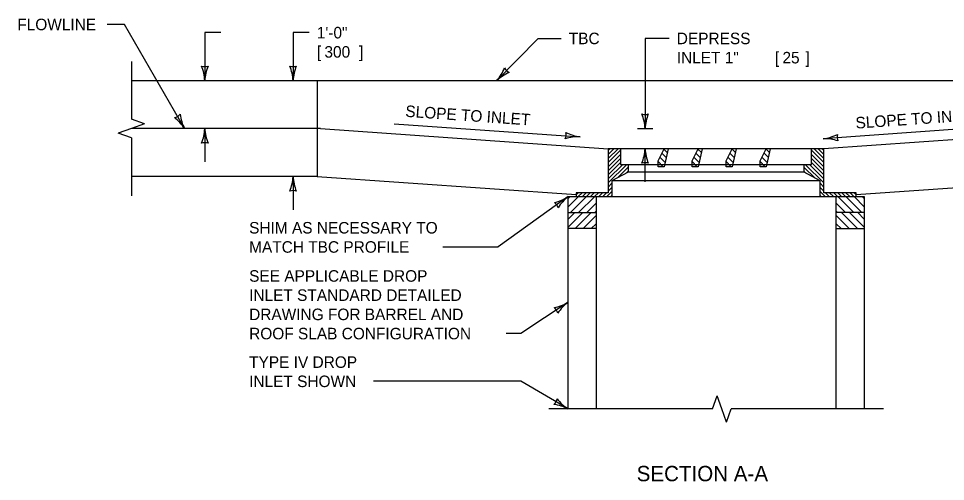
# Model space of a CAD drawing. Extents: x 49991.4 to 50048.3, y 49987.6 to 50018.3.
# Drawn here: x 50039.916 to 50044.738, y 50001.927 to 50004.338 of the extents above; entities that cross this region are included whole.
import ezdxf

# ---------------------------------------------------------------- set-up
doc = ezdxf.new("R2010")
doc.units = 0
for name, color, linetype in [('Level 1', 7, 'Continuous'), ('Level 2', 7, 'Continuous'), ('Level 3', 7, 'Continuous'), ('Level 4', 7, 'Continuous'), ('Level 6', 7, 'Continuous')]:
    doc.layers.add(name, color=color, linetype=linetype)

msp = doc.modelspace()

# ---------------------------------------------------------------- linework, layer by layer
at = {"layer": 'Level 1'}
for p, q in [((50046.6203, 50004.0142), (50040.5028, 50004.0142)), ((50041.4694, 50004.0142), (50041.4694, 50003.5154)), ((50041.4694, 50003.7648), (50040.5028, 50003.7648)), ((50041.4869, 50003.7648), (50041.4694, 50003.7648)), ((50041.4869, 50003.7648), (50042.9832, 50003.6602)), ((50045.6016, 50003.7648), (50044.1053, 50003.6602)), ((50042.9832, 50003.6602), (50042.9832, 50003.4305)), ((50044.1053, 50003.6602), (50042.9832, 50003.6602)), ((50043.0345, 50003.6602), (50042.9832, 50003.6089)), ((50043.0133, 50003.6602), (50042.9832, 50003.6301)), ((50042.9921, 50003.6602), (50042.9832, 50003.6513)), ((50043.0472, 50003.6516), (50042.9832, 50003.5877)), ((50043.0472, 50003.6602), (50043.0472, 50003.5782)), ((50043.2431, 50003.5977), (50043.2744, 50003.6602)), ((50043.2908, 50003.6404), (50043.2733, 50003.658)), ((50043.2952, 50003.6602), (50043.2744, 50003.5664)), ((50043.4202, 50003.5977), (50043.4515, 50003.6602)), ((50043.4679, 50003.6404), (50043.4503, 50003.658)), ((50043.4723, 50003.6602), (50043.4515, 50003.5664)), ((50043.5973, 50003.5977), (50043.6285, 50003.6602)), ((50043.645, 50003.6404), (50043.6274, 50003.658)), ((50043.6494, 50003.6602), (50043.6285, 50003.5664)), ((50043.7744, 50003.5977), (50043.8056, 50003.6602)), ((50043.8221, 50003.6404), (50043.8045, 50003.658)), ((50043.8265, 50003.6602), (50043.8056, 50003.5664)), ((50044.0413, 50003.5782), (50044.0413, 50003.6602)), ((50044.0413, 50003.6516), (50044.1053, 50003.5877)), ((50044.0539, 50003.6602), (50044.1053, 50003.6089)), ((50044.0751, 50003.6602), (50044.1053, 50003.6301)), ((50044.0963, 50003.6602), (50044.1053, 50003.6513)), ((50044.1053, 50003.4305), (50044.1053, 50003.6602)), ((50043.0472, 50003.6304), (50042.9832, 50003.5664)), ((50043.0472, 50003.6092), (50042.9832, 50003.5452)), ((50043.2792, 50003.5883), (50043.2521, 50003.6155)), ((50043.285, 50003.6144), (50043.2627, 50003.6368)), ((50043.4563, 50003.5883), (50043.4291, 50003.6155)), ((50043.4621, 50003.6144), (50043.4397, 50003.6368)), ((50043.6334, 50003.5883), (50043.6062, 50003.6155)), ((50043.6392, 50003.6144), (50043.6168, 50003.6368)), ((50043.8105, 50003.5883), (50043.7833, 50003.6155)), ((50043.8163, 50003.6144), (50043.7939, 50003.6368)), ((50044.0413, 50003.6304), (50044.1053, 50003.5664)), ((50044.0413, 50003.6092), (50044.1053, 50003.5452)), ((50043.0472, 50003.588), (50042.9832, 50003.524)), ((50043.0798, 50003.5782), (50042.9832, 50003.4816)), ((50043.0586, 50003.5782), (50042.9832, 50003.5028)), ((50043.0849, 50003.5621), (50043.0308, 50003.5079)), ((50043.0472, 50003.5782), (50043.0866, 50003.5782)), ((50043.0866, 50003.5782), (50043.0866, 50003.5372)), ((50043.2431, 50003.5664), (50043.2431, 50003.5977)), ((50043.2693, 50003.5664), (50043.2431, 50003.5926)), ((50043.2744, 50003.5664), (50043.2431, 50003.5664)), ((50043.4202, 50003.5664), (50043.4202, 50003.5977)), ((50043.4464, 50003.5664), (50043.4202, 50003.5926)), ((50043.4515, 50003.5664), (50043.4202, 50003.5664)), ((50043.5973, 50003.5664), (50043.5973, 50003.5977)), ((50043.6235, 50003.5664), (50043.5973, 50003.5926)), ((50043.6285, 50003.5664), (50043.5973, 50003.5664)), ((50043.7744, 50003.5664), (50043.7744, 50003.5977)), ((50043.8006, 50003.5664), (50043.7744, 50003.5926)), ((50043.8056, 50003.5664), (50043.7744, 50003.5664)), ((50044.0035, 50003.5372), (50044.0035, 50003.5782)), ((50044.0035, 50003.5782), (50044.0413, 50003.5782)), ((50044.0035, 50003.5621), (50044.0577, 50003.5079)), ((50044.0087, 50003.5782), (50044.1053, 50003.4816)), ((50044.0299, 50003.5782), (50044.1053, 50003.5028)), ((50044.0413, 50003.588), (50044.1053, 50003.524)), ((50041.4694, 50003.5154), (50040.5028, 50003.5154)), ((50041.4694, 50003.5154), (50042.8159, 50003.4213)), ((50043.0866, 50003.5372), (50043.0029, 50003.4929)), ((50043.0849, 50003.5409), (50043.0769, 50003.5328)), ((50044.0035, 50003.5409), (50044.0116, 50003.5328)), ((50044.0856, 50003.4929), (50044.0035, 50003.5372)), ((50044.2726, 50003.4213), (50045.619, 50003.5154)), ((50043.0029, 50003.4801), (50042.9832, 50003.4604)), ((50043.0029, 50003.4588), (50042.9832, 50003.4392)), ((50043.0029, 50003.4929), (50043.0029, 50003.4109)), ((50044.0856, 50003.4929), (50043.0029, 50003.4929)), ((50044.0856, 50003.4109), (50044.0856, 50003.4929)), ((50044.0856, 50003.4801), (50044.1053, 50003.4604)), ((50044.0856, 50003.4588), (50044.1053, 50003.4392)), ((50042.7749, 50002.3052), (50042.7749, 50003.4109)), ((50042.7749, 50003.4109), (50044.1692, 50003.4109)), ((50042.7749, 50003.3578), (50042.828, 50003.4109)), ((50042.7749, 50003.4002), (50042.7855, 50003.4109)), ((50042.7871, 50003.3275), (50042.8704, 50003.4109)), ((50042.9832, 50003.4305), (50042.8159, 50003.4305)), ((50042.8159, 50003.4305), (50042.8159, 50003.4109)), ((50042.8261, 50003.4305), (50042.8159, 50003.4203)), ((50042.8473, 50003.4305), (50042.8276, 50003.4109)), ((50042.8295, 50003.3275), (50042.9128, 50003.4109)), ((50042.8685, 50003.4305), (50042.8488, 50003.4109)), ((50042.8897, 50003.4305), (50042.87, 50003.4109)), ((50042.9109, 50003.4305), (50042.8913, 50003.4109)), ((50042.9322, 50003.4305), (50042.9125, 50003.4109)), ((50042.9209, 50003.4109), (50042.9209, 50002.3052)), ((50042.9534, 50003.4305), (50042.9337, 50003.4109)), ((50042.9746, 50003.4305), (50042.9549, 50003.4109)), ((50043.0029, 50003.4376), (50042.9761, 50003.4109)), ((50043.0029, 50003.4164), (50042.9973, 50003.4109)), ((50044.0856, 50003.4376), (50044.1123, 50003.4109)), ((50044.0856, 50003.4164), (50044.0911, 50003.4109)), ((50044.2726, 50003.4305), (50044.1053, 50003.4305)), ((50044.1139, 50003.4305), (50044.1336, 50003.4109)), ((50044.1351, 50003.4305), (50044.1548, 50003.4109)), ((50044.1563, 50003.4305), (50044.176, 50003.4109)), ((50044.1692, 50002.3052), (50044.1692, 50003.4109)), ((50044.1692, 50003.4109), (50044.3152, 50003.4109)), ((50044.2606, 50003.3275), (50044.1773, 50003.4109)), ((50044.1775, 50003.4305), (50044.1972, 50003.4109)), ((50044.1987, 50003.4305), (50044.2184, 50003.4109)), ((50044.303, 50003.3275), (50044.2197, 50003.4109)), ((50044.2199, 50003.4305), (50044.2396, 50003.4109)), ((50044.2412, 50003.4305), (50044.2608, 50003.4109)), ((50044.3152, 50003.3578), (50044.2621, 50003.4109)), ((50044.2624, 50003.4305), (50044.2726, 50003.4203)), ((50044.2726, 50003.4109), (50044.2726, 50003.4305)), ((50044.3152, 50003.4002), (50044.3046, 50003.4109)), ((50044.3152, 50003.4109), (50044.3152, 50002.3052)), ((50042.8719, 50003.3275), (50042.9209, 50003.3765)), ((50044.2182, 50003.3275), (50044.1692, 50003.3765)), ((50042.7749, 50003.3275), (50042.9209, 50003.3275)), ((50042.7749, 50003.2509), (50042.8515, 50003.3275)), ((50042.7749, 50003.2934), (50042.809, 50003.3275)), ((50042.8106, 50003.2442), (50042.8939, 50003.3275)), ((50042.853, 50003.2442), (50042.9209, 50003.3121)), ((50042.9143, 50003.3275), (50042.9209, 50003.334)), ((50044.1758, 50003.3275), (50044.1692, 50003.334)), ((50044.3152, 50003.3275), (50044.1692, 50003.3275)), ((50044.2371, 50003.2442), (50044.1692, 50003.3121)), ((50044.2795, 50003.2442), (50044.1962, 50003.3275)), ((50044.3152, 50003.2509), (50044.2386, 50003.3275)), ((50044.3152, 50003.2934), (50044.2811, 50003.3275)), ((50042.8954, 50003.2442), (50042.9209, 50003.2696)), ((50044.1947, 50003.2442), (50044.1692, 50003.2696)), ((50042.9209, 50003.2442), (50042.7749, 50003.2442)), ((50044.1692, 50003.2442), (50044.3152, 50003.2442))]:
    msp.add_line(p, q, dxfattribs=at)
at = {"layer": 'Level 3'}
for p, q in [((50040.4663, 50004.3069), (50040.3758, 50004.3069)), ((50040.7792, 50003.7648), (50040.4663, 50004.3069)), ((50040.9678, 50004.2642), (50040.8845, 50004.2642)), ((50040.8845, 50004.2642), (50040.8845, 50004.0142)), ((50041.4272, 50004.2642), (50041.3439, 50004.2642)), ((50041.3439, 50004.2642), (50041.3439, 50004.0142)), ((50042.4029, 50004.0142), (50042.6181, 50004.2342)), ((50042.6181, 50004.2342), (50042.7381, 50004.2342)), ((50043.3, 50004.2342), (50043.175, 50004.2342)), ((50043.175, 50004.2342), (50043.175, 50003.7648)), ((50040.8845, 50003.7648), (50040.8845, 50003.5914)), ((50041.8704, 50003.7902), (50042.8372, 50003.7226)), ((50043.135, 50003.7648), (50043.215, 50003.7648)), ((50045.162, 50003.7863), (50044.1016, 50003.7122)), ((50043.175, 50003.4868), (50043.175, 50003.6602)), ((50041.3438, 50003.5154), (50041.3439, 50003.342)), ((50042.7749, 50003.4109), (50042.4099, 50003.1484)), ((50042.1221, 50003.1484), (50042.4099, 50003.1484)), ((50042.7749, 50002.8604), (50042.5292, 50002.6975)), ((50042.5292, 50002.6975), (50042.4525, 50002.6975)), ((50042.5292, 50002.4489), (50041.7625, 50002.4489)), ((50042.7749, 50002.3052), (50042.5292, 50002.4489))]:
    msp.add_line(p, q, dxfattribs=at)
for centre, radius, start, end in [((50040.8845, 50004.1424), 0.0548, 252.1388, 287.8612), ((50040.6518, 50004.0027), 0.233, 2.8273, 22.0772), ((50041.1066, 50004.0051), 0.2223, 157.456, 177.6395), ((50041.3439, 50004.1424), 0.0548, 252.1388, 287.8612), ((50041.1112, 50004.0027), 0.233, 2.8273, 22.0772), ((50041.566, 50004.0051), 0.2223, 157.456, 177.6395), ((50042.2285, 50004.1687), 0.233, 318.4572, 337.707), ((50042.5553, 50003.8523), 0.2223, 113.0859, 133.2694), ((50042.4926, 50004.1059), 0.0548, 207.7687, 243.491), ((50043.175, 50003.893), 0.0548, 252.1388, 287.8612), ((50042.9423, 50003.7533), 0.233, 2.8273, 22.0772), ((50043.3972, 50003.7557), 0.2223, 157.456, 177.6395), ((50040.7151, 50003.8759), 0.0548, 282.1388, 317.8612), ((50040.5834, 50003.6385), 0.233, 32.8273, 52.0772), ((50040.9762, 50003.868), 0.2223, 187.456, 207.6395), ((50040.6623, 50003.774), 0.2223, 337.456, 357.6395), ((50041.1172, 50003.7763), 0.233, 182.8273, 202.0772), ((50042.7093, 50003.7316), 0.0548, 338.1388, 13.8612), ((50042.8618, 50003.9436), 0.2223, 243.456, 263.6395), ((50042.8324, 50003.4897), 0.233, 88.8273, 108.0772), ((50044.0739, 50003.9435), 0.233, 276.8273, 296.0772), ((50044.108, 50003.4899), 0.2223, 71.456, 91.6395), ((50044.2295, 50003.7211), 0.0548, 166.1388, 201.8612), ((50040.8845, 50003.6366), 0.0548, 72.1388, 107.8612), ((50042.9529, 50003.6694), 0.2223, 337.456, 357.6395), ((50043.4077, 50003.6717), 0.233, 182.8273, 202.0772), ((50043.175, 50003.532), 0.0548, 72.1388, 107.8612), ((50041.1217, 50003.5246), 0.2223, 337.456, 357.6395), ((50041.5766, 50003.5269), 0.233, 182.8273, 202.0772), ((50041.3438, 50003.3872), 0.0548, 72.1388, 107.8612), ((50042.6526, 50003.5965), 0.2223, 283.1806, 303.3641), ((50042.9201, 50003.2286), 0.233, 128.5519, 147.8018), ((50042.6708, 50003.336), 0.0548, 17.8634, 53.5858), ((50042.6597, 50003.0506), 0.2223, 281.0074, 301.1909), ((50042.668, 50002.7896), 0.0548, 15.6902, 51.4126), ((50042.9131, 50002.6729), 0.233, 126.3787, 145.6286), ((50042.6642, 50002.3699), 0.0548, 311.8181, 347.5404), ((50042.8949, 50002.4923), 0.2223, 217.1353, 237.3188), ((50042.6673, 50002.0985), 0.233, 62.5066, 81.7564)]:
    msp.add_arc(centre, radius, start, end, dxfattribs=at)
at = {"layer": 'Level 4'}
for p, q in [((50043.0866, 50003.5782), (50044.0035, 50003.5782)), ((50044.0035, 50003.5372), (50043.0866, 50003.5372))]:
    msp.add_line(p, q, dxfattribs=at)
at = {"layer": 'Level 6'}
for p, q in [((50040.5028, 50004.1142), (50040.5028, 50003.8134)), ((50040.5714, 50003.7891), (50040.5028, 50003.8134)), ((50040.5028, 50003.7648), (50040.4342, 50003.7405)), ((50040.5714, 50003.7891), (50040.5028, 50003.7648)), ((50040.5028, 50003.7162), (50040.4342, 50003.7405)), ((50040.5028, 50003.7162), (50040.5028, 50003.4154)), ((50043.5261, 50002.3052), (50043.5504, 50002.3738)), ((50043.5747, 50002.3052), (50043.5504, 50002.3738)), ((50043.5261, 50002.3052), (50042.6749, 50002.3052)), ((50043.599, 50002.2366), (50043.5747, 50002.3052)), ((50043.599, 50002.2366), (50043.6233, 50002.3052)), ((50044.4152, 50002.3052), (50043.6233, 50002.3052))]:
    msp.add_line(p, q, dxfattribs=at)

# ---------------------------------------------------------------- texts
at = {"layer": 'Level 2'}
for s, height, p in [('FLOWLINE', 0.06, (50039.909, 50004.2769)), ('1\'-0"', 0.06, (50041.4672, 50004.2342)), ('TBC', 0.06, (50042.7781, 50004.2042)), ('DEPRESS', 0.06, (50043.34, 50004.2042)), ('[', 0.06, (50041.4672, 50004.1342)), ('300', 0.06, (50041.5069, 50004.1342)), (']', 0.06, (50041.6869, 50004.1342)), ('INLET 1" ', 0.06, (50043.34, 50004.1042)), ('[', 0.06, (50043.85, 50004.1042)), ('25', 0.06, (50043.8897, 50004.1042)), (']', 0.06, (50044.0097, 50004.1042)), ('SHIM AS NECESSARY TO ', 0.06, (50041.1152, 50003.2184)), ('MATCH TBC PROFILE', 0.06, (50041.1152, 50003.1184)), ('SEE APPLICABLE DROP', 0.06, (50041.1152, 50002.9675)), ('INLET STANDARD DETAILED', 0.06, (50041.1152, 50002.8675)), ('DRAWING FOR BARREL AND', 0.06, (50041.1152, 50002.7675)), ('ROOF SLAB CONFIGURATION', 0.06, (50041.1152, 50002.6675)), ('TYPE IV DROP', 0.06, (50041.1152, 50002.5189)), ('INLET SHOWN', 0.06, (50041.1152, 50002.4189)), ('SECTION A-A', 0.08, (50043.1313, 50001.9286))]:
    msp.add_text(s, height=height, dxfattribs=at).set_placement(p)
for rotation, p in [(356, (50041.9263, 50003.8264)), (4, (50044.272, 50003.7642))]:
    msp.add_text('SLOPE TO INLET', height=0.06, rotation=rotation, dxfattribs=at).set_placement(p)

doc.saveas('drawing.dxf')
